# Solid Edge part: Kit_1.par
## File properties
Sűrűség: 0,000 kg/m^3
Pontosság: 0,990
Author: ahadarics
Last saved by: psaghy
Revision: 80
Username: ahadarics
Dokumentum tartalom típus: 0
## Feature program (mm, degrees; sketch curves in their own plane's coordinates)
base feature "unnamed BaseFeature 1"
sketch for "Furat_1" plane through (0, 0, 32.5) normal (0, 0, 1) x-axis (0, -1, 0)
  hole centre (-16.25, 16.25) bore radius 2.4585
hole "Furat_1" nominal diameter 6 finite  VBottomAngle = 118 deg
sketch for "unnamed Hole 1" plane through (0, 0, 32.5) normal (0, 0, 1) x-axis (0, -1, 0)
  hole centre (-16.25, -16.25) bore radius 2.4585
hole "unnamed Hole 1" finite
sketch for "unnamed Hole 2" plane through (0, 0, 32.5) normal (0, 0, 1) x-axis (0, -1, 0)
  hole centre (16.25, -16.25) bore radius 2.4585
hole "unnamed Hole 2" finite
sketch for "unnamed Hole 3" plane through (0, 0, 32.5) normal (0, 0, 1) x-axis (0, -1, 0)
  hole centre (16.25, 16.25) bore radius 2.4585
hole "unnamed Hole 3" finite
pattern "unnamed Pattern 1" of "Furat_1", "unnamed Hole 1", "unnamed Hole 2", "unnamed Hole 3"
sketch for "Furat_5" plane through (23.5, 0.0133, 16.7488) normal (1, 0, 0) x-axis (0, 0, -1)
hole "Furat_5" diameter 9.728 finite  ThreadDepth = 9 mm
chamfer "Letörés_1" setback 0.9
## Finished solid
Body 1: solid body, 384 faces, 919 edges, 587 vertices, 3 internal voids.
  Faces by surface: cylinder 131, plane 125, cone 46, torus 39, spline 31, sphere 10, swept 2
  Edges by curve: circle 312, curve on surface 296, line 295, spline 16
Bounding box of the edges (mm; curved faces can reach further): 47.001 x 47.000 x 44.500, from (-23.5, -23.5, 6) to (23.5005, 23.5, 50.5).
Cylindrical faces by radius (mm): R0.2287 x1, R0.2297 x1, R0.2305 x1, R0.232 x1, R0.2354 x1, R0.2616 x1, R0.2684 x1, R0.2696 x1, R0.274 x1, R0.2809 x1, R0.2869 x1, R0.2897 x2, R0.2949 x1, R0.2975 x1, R0.2999 x1, R0.3047 x1, R0.3049 x1, R0.3054 x1, R0.3191 x1, R0.3251 x1, R0.3471 x1, R0.361 x1, R0.3789 x1, R0.3925 x1, R0.3994 x1, R0.4078 x1, R0.4206 x1, R0.4339 x1, R0.4364 x1, R0.4536 x1, R0.4559 x1, R0.4564 x1, R0.4771 x1, R0.4781 x1, R0.5 x7, R0.5094 x1, R0.5174 x1, R0.5354 x1, R0.5534 x1, R0.6836 x1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
Conical faces (half-angle, radius in mm at the cone's reference point): 1.6538 deg R7.75 x1, 3.5477 deg R8.7454 x1, 5.1549 deg R0.4847 x1, 5.762 deg R6.4 x1, 11.1239 deg R6.0056 x1, 15 deg R13.6406 x1, 15.3654 deg R6.7214 x1, 19.3654 deg R7.1921 x1, 25.0169 deg R10.31 x1, 27.5528 deg R20.5 x4, 30 deg R4.0866 x1, 30 deg R7.8557 x2, 30 deg R8.1443 x1, 30 deg R14.5 x1, 45 deg R1.1 x1, 45 deg R2.3 x1, 45 deg R2.4 x1, 45 deg R3.25 x8, 45 deg R4.85 x8, 45 deg R5.183 x1, 45 deg R6.15 x2, 45 deg R11.25 x1, 59 deg R1.75 x1, 59 deg R2.4585 x4
Toroidal faces (ring radius, tube radius in mm): R0.7228 r0.5 x1, R0.8364 r0.5 x1, R1.4663 r0.5006 x3, R3.3 r0.3 x4, R3.6 r0.4 x1, R3.7 r0.3 x1, R4.95 r0.2 x4, R5.65 r0.5 x4, R6.3 r0.3 x1, R6.3085 r0.3 x1, R7.4279 r0.25 x1, R7.75 r0.5 x1, R8 r0.5 x1, R8.2464 r0.5 x1, R10.8 r0.2 x1, R12 r2 x1, R12.8663 r0.5 x1, R15.5 r0.5 x1, R18 r1 x3, R22.5 r1 x6, R23.8031 r0.5 x1
Spherical faces by radius (mm): R0.5 x4, R1 x6
Planar faces by outward normal: +x 19, +y 9, +z 29, -x 2, -y 9, -z 17, oblique 40
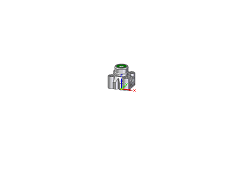
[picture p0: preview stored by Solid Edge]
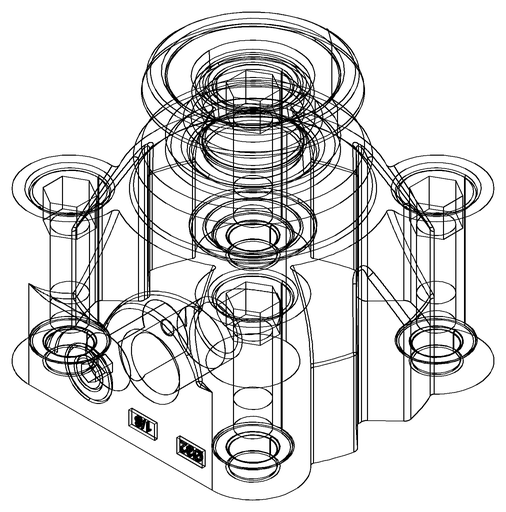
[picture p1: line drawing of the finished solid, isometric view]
